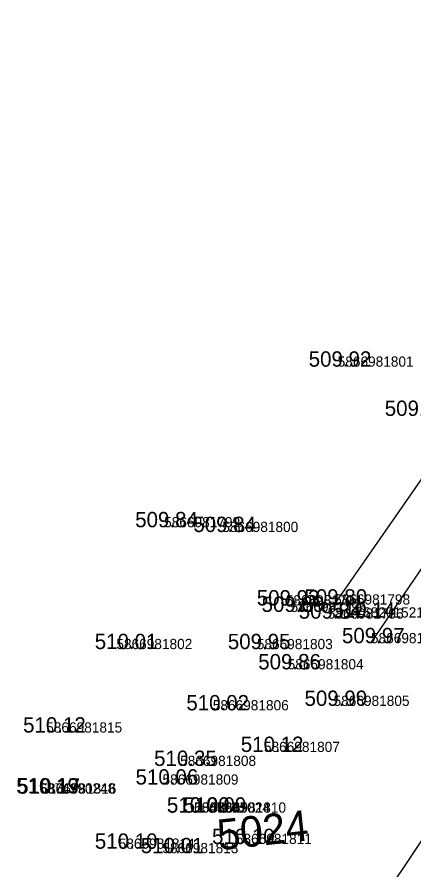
# Model space of a CAD drawing. Extents: x -669251 to -668549, y -1128351 to -1127698.
# Drawn here: x -668747.68 to -668728.25, y -1127996.27 to -1127954.56 of the extents above; entities that cross this region are included whole.
import ezdxf

# ---------------------------------------------------------------- set-up
doc = ezdxf.new("R2010")
doc.units = 0
for name, color, linetype in [('Vrstva 1', 7, 'Continuous'), ('Vrstva 10', 7, 'Continuous'), ('Vrstva 2', 7, 'Continuous'), ('Vrstva 3', 7, 'Continuous'), ('Vrstva 63', 7, 'Continuous')]:
    doc.layers.add(name, color=color, linetype=linetype)

msp = doc.modelspace()

# ---------------------------------------------------------------- linework, layer by layer
at = {"layer": 'Vrstva 1'}
for p, q in [((-668731.982, -1127971.661), (-668731.982, -1127971.661)), ((-668728.261, -1127974.069), (-668728.261, -1127974.069)), ((-668740.478, -1127979.515), (-668740.478, -1127979.515)), ((-668737.631, -1127979.748), (-668737.631, -1127979.748)), ((-668734.523, -1127983.337), (-668734.523, -1127983.337)), ((-668734.287, -1127983.656), (-668734.287, -1127983.656)), ((-668732.155, -1127983.295), (-668732.155, -1127983.295)), ((-668732.471, -1127983.986), (-668732.471, -1127983.986)), ((-668731.11, -1127983.93), (-668731.11, -1127983.93)), ((-668730.353, -1127985.185), (-668730.353, -1127985.185)), ((-668742.818, -1127985.474), (-668742.818, -1127985.474)), ((-668735.94, -1127985.477), (-668735.94, -1127985.477)), ((-668734.431, -1127986.465), (-668734.431, -1127986.465)), ((-668732.183, -1127988.252), (-668732.183, -1127988.252)), ((-668738.096, -1127988.47), (-668738.096, -1127988.47)), ((-668746.251, -1127989.555), (-668746.251, -1127989.555)), ((-668735.593, -1127990.505), (-668735.593, -1127990.505)), ((-668739.695, -1127991.189), (-668739.695, -1127991.189)), ((-668740.559, -1127992.101), (-668740.559, -1127992.101)), ((-668746.585, -1127992.536), (-668746.585, -1127992.536)), ((-668746.537, -1127992.544), (-668746.537, -1127992.544)), ((-668739.014, -1127993.474), (-668739.014, -1127993.474)), ((-668739.014, -1127993.474), (-668739.014, -1127993.474)), ((-668739.01, -1127993.47), (-668739.01, -1127993.47)), ((-668738.229, -1127993.473), (-668738.229, -1127993.473)), ((-668742.703, -1127995.238), (-668742.703, -1127995.238)), ((-668736.966, -1127995.008), (-668736.966, -1127995.008)), ((-668740.563, -1127995.455), (-668740.563, -1127995.455))]:
    msp.add_line(p, q, dxfattribs=at)
at = {"layer": 'Vrstva 10'}
for p, q in [((-668700.958, -1127954.561), (-668730.831, -1127999.239)), ((-668720.53, -1127966.58), (-668732.155, -1127983.295)), ((-668730.353, -1127985.185), (-668718.583, -1127967.884))]:
    msp.add_line(p, q, dxfattribs=at)

# ---------------------------------------------------------------- texts
at = {"layer": 'Vrstva 2'}
for s, p in [('5866981801', (-668731.982, -1127971.661)), ('5866981799', (-668740.478, -1127979.515)), ('5866981800', (-668737.631, -1127979.748)), ('5866981794', (-668734.523, -1127983.337)), ('5866981798', (-668732.155, -1127983.295)), ('5866981795', (-668734.287, -1127983.656)), ('5866981796', (-668732.471, -1127983.986)), ('7682015214', (-668731.11, -1127983.93)), ('5866981797', (-668730.353, -1127985.185)), ('5866981802', (-668742.818, -1127985.474)), ('5866981803', (-668735.94, -1127985.477)), ('5866981804', (-668734.431, -1127986.465)), ('5866981805', (-668732.183, -1127988.252)), ('5866981806', (-668738.096, -1127988.47)), ('5866981815', (-668746.251, -1127989.555)), ('5866981807', (-668735.593, -1127990.505)), ('5866981808', (-668739.695, -1127991.189)), ('5866981809', (-668740.559, -1127992.101)), ('6374990248', (-668746.585, -1127992.536)), ('5866981816', (-668746.537, -1127992.544)), ('5867015024', (-668739.014, -1127993.474)), ('5866985024', (-668739.01, -1127993.47)), ('6043035024', (-668739.014, -1127993.474)), ('5866981810', (-668738.229, -1127993.473)), ('5866981811', (-668736.966, -1127995.008)), ('5866981814', (-668742.703, -1127995.238)), ('5866981813', (-668740.563, -1127995.455))]:
    msp.add_text(s, height=0.5, dxfattribs=at).set_placement(p)
at = {"layer": 'Vrstva 3'}
for s, p in [('509.92 ', (-668733.401, -1127971.661)), ('509.73 ', (-668729.678, -1127974.069)), ('509.84 ', (-668741.895, -1127979.515)), ('509.84 ', (-668739.048, -1127979.748)), ('509.93 ', (-668735.942, -1127983.337)), ('509.80 ', (-668733.608, -1127983.295)), ('509.89 ', (-668735.707, -1127983.656)), ('509.84 ', (-668733.888, -1127983.986)), ('510.14 ', (-668732.242, -1127983.93)), ('509.97 ', (-668731.772, -1127985.185)), ('510.01 ', (-668743.876, -1127985.474)), ('509.95 ', (-668737.359, -1127985.477)), ('509.86 ', (-668735.871, -1127986.465)), ('510.02 ', (-668739.391, -1127988.47)), ('509.99 ', (-668733.605, -1127988.252)), ('510.12 ', (-668747.383, -1127989.555)), ('510.12 ', (-668736.725, -1127990.505)), ('510.35 ', (-668740.969, -1127991.189)), ('510.06 ', (-668741.877, -1127992.101)), ('510.19 ', (-668747.72, -1127992.536)), ('510.17 ', (-668747.669, -1127992.544)), ('510.00 ', (-668740.344, -1127993.474)), ('510.00 ', (-668740.344, -1127993.474)), ('510.00 ', (-668740.34, -1127993.47)), ('510.09 ', (-668739.527, -1127993.473)), ('510.10 ', (-668743.871, -1127995.238)), ('510.10 ', (-668738.134, -1127995.008)), ('510.01 ', (-668741.621, -1127995.455))]:
    msp.add_text(s, height=0.75, dxfattribs=at).set_placement(p)
at = {"layer": 'Vrstva 63'}
msp.add_text('5024', height=1.5, rotation=6.3651, dxfattribs=at).set_placement((-668737.788, -1127995.32))

doc.saveas('drawing.dxf')
